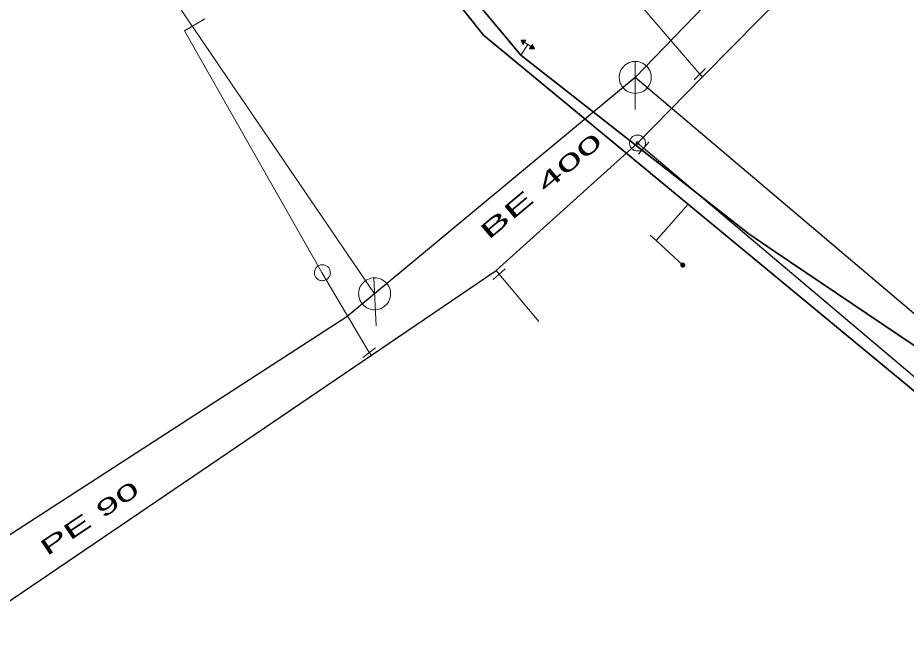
# Model space of a CAD drawing. Extents: x -779496 to -779026, y -977086 to -976624.
# Drawn here: x -779315.3 to -779259.7, y -976922.6 to -976883.2 of the extents above; entities that cross this region are included whole.
import ezdxf

# ---------------------------------------------------------------- set-up
doc = ezdxf.new("R2010")
doc.units = 0
doc.header["$LTSCALE"] = 0.4
doc.linetypes.add('MEDIUM_DASHED', pattern=[4.5, 3, -1.5])
for name, color, linetype, lineweight in [('1', 7, 'MEDIUM_DASHED', 25), ('11', 7, 'Continuous', 13), ('13', 7, 'Continuous', 13), ('14', 7, 'Continuous', 13), ('17', 7, 'Continuous', 25), ('22', 7, 'Continuous', 13), ('23', 7, 'Continuous', 13), ('34', 7, 'Continuous', 13), ('47', 7, 'Continuous', 13), ('9', 7, 'Continuous', 13)]:
    doc.layers.add(name, color=color, linetype=linetype, lineweight=lineweight)

msp = doc.modelspace()

# ---------------------------------------------------------------- linework, layer by layer
at = {"layer": '11'}
msp.add_line((-779306.139, -976881.166), (-779292.98, -976900.507), dxfattribs=at)
at = {"layer": '13'}
for p, q in [((-779272.656, -976886.759), (-779278.993, -976879.365)), ((-779293.314, -976904.181), (-779296.277, -976899.18)), ((-779282.71, -976902.234), (-779285.188, -976899.282))]:
    msp.add_line(p, q, dxfattribs=at)
msp.add_lwpolyline([(-779296.277, -976899.18), (-779304.857, -976884.055), (-779303.587, -976883.314)], dxfattribs=at)
at = {"layer": '14', "lineweight": 25}
for p, q in [((-779276.684, -976886.967), (-779292.98, -976900.507)), ((-779241.75, -976916.623), (-779276.684, -976886.967))]:
    msp.add_line(p, q, dxfattribs=at)
at = {"layer": '14'}
for p, q in [((-779272.473, -976886.943), (-779272.656, -976886.759)), ((-779276.545, -976891.073), (-779276.159, -976891.399)), ((-779273.375, -976894.904), (-779275.376, -976897.173)), ((-779275.376, -976897.173), (-779273.715, -976898.706)), ((-779285.388, -976899.059), (-779285.188, -976899.282)), ((-779293.182, -976904.354), (-779293.314, -976904.181))]:
    msp.add_line(p, q, dxfattribs=at)
at = {"layer": '14', "lineweight": 25}
for points in [[(-779257.611, -976867.208), (-779265.041, -976874.906), (-779276.684, -976886.967)], [(-779292.98, -976900.507), (-779294.713, -976901.947), (-779319.548, -976918.006), (-779350.848, -976937.607), (-779353.627, -976939.656), (-779370.105, -976951.862)]]:
    msp.add_lwpolyline(points, dxfattribs=at)
at = {"layer": '17'}
for points in [[(-779276.545, -976891.073), (-779272.473, -976886.943), (-779252.653, -976866.844), (-779246.603, -976859.784), (-779242.228, -976854.603), (-779234.164, -976845.175), (-779227.585, -976837.452), (-779212.579, -976818.883), (-779210.76, -976816.627), (-779191.487, -976792.772), (-779191.372, -976792.629), (-779190.682, -976791.787), (-779189.552, -976790.451), (-779187.15, -976792.396)], [(-779365.489, -976951.461), (-779357.531, -976946.544), (-779351.454, -976942.87), (-779336.305, -976933.651), (-779293.182, -976904.354), (-779285.388, -976899.059), (-779276.545, -976891.073)], [(-779226.798, -976933.215), (-779233.45, -976927.57), (-779243.764, -976918.817), (-779248.891, -976914.465), (-779251.398, -976912.338), (-779255.068, -976909.223), (-779276.159, -976891.399)]]:
    msp.add_lwpolyline(points, dxfattribs=at)
at = {"layer": '17', "lineweight": 35}
for points in [[(-779314.495, -976791.582), (-779291.37, -976876.552), (-779283.847, -976885.578)], [(-779294.52, -976873.809), (-779286.179, -976884.319), (-779226.903, -976933.326), (-779213.28, -976944.579), (-779208.355, -976950.874)], [(-779283.847, -976885.578), (-779269.588, -976896.763), (-779267.93, -976897.881), (-779206.76, -976939.131), (-779203.521, -976944.031)]]:
    msp.add_lwpolyline(points, dxfattribs=at)
at = {"layer": '22'}
for p, q in [((-779276.684, -976888.967), (-779276.683, -976885.967)), ((-779292.883, -976902.505), (-779293.028, -976899.508))]:
    msp.add_line(p, q, dxfattribs=at)
for points in [[(-779275.684, -976886.967), (-779275.689, -976886.858), (-779275.707, -976886.75), (-779275.737, -976886.644), (-779275.777, -976886.543), (-779275.829, -976886.446), (-779275.891, -976886.356), (-779275.963, -976886.273), (-779276.043, -976886.199), (-779276.131, -976886.133), (-779276.225, -976886.078), (-779276.325, -976886.033), (-779276.43, -976886), (-779276.537, -976885.978), (-779276.646, -976885.968), (-779276.756, -976885.97), (-779276.864, -976885.984), (-779276.971, -976886.009), (-779277.074, -976886.046), (-779277.172, -976886.095), (-779277.264, -976886.153), (-779277.35, -976886.222), (-779277.427, -976886.299), (-779277.496, -976886.385), (-779277.555, -976886.477), (-779277.603, -976886.575), (-779277.64, -976886.678), (-779277.666, -976886.785), (-779277.68, -976886.893), (-779277.683, -976887.003), (-779277.673, -976887.112), (-779277.652, -976887.219), (-779277.618, -976887.323), (-779277.574, -976887.423), (-779277.519, -976887.518), (-779277.453, -976887.606), (-779277.379, -976887.686), (-779277.296, -976887.758), (-779277.206, -976887.82), (-779277.11, -976887.872), (-779277.008, -976887.913), (-779276.903, -976887.943), (-779276.795, -976887.961), (-779276.685, -976887.967), (-779276.576, -976887.961), (-779276.468, -976887.943), (-779276.363, -976887.914), (-779276.261, -976887.873), (-779276.164, -976887.821), (-779276.074, -976887.759), (-779275.991, -976887.688), (-779275.916, -976887.608), (-779275.851, -976887.52), (-779275.795, -976887.426), (-779275.751, -976887.326), (-779275.717, -976887.222), (-779275.695, -976887.114), (-779275.685, -976887.005)], [(-779291.981, -976900.459), (-779291.992, -976900.35), (-779292.015, -976900.243), (-779292.05, -976900.139), (-779292.095, -976900.04), (-779292.152, -976899.945), (-779292.218, -976899.859), (-779292.294, -976899.779), (-779292.377, -976899.709), (-779292.468, -976899.647), (-779292.565, -976899.597), (-779292.667, -976899.557), (-779292.773, -976899.529), (-779292.881, -976899.512), (-779292.991, -976899.507), (-779293.1, -976899.515), (-779293.208, -976899.534), (-779293.313, -976899.564), (-779293.414, -976899.606), (-779293.51, -976899.66), (-779293.599, -976899.722), (-779293.682, -976899.795), (-779293.755, -976899.876), (-779293.82, -976899.965), (-779293.874, -976900.06), (-779293.917, -976900.16), (-779293.949, -976900.264), (-779293.97, -976900.373), (-779293.979, -976900.481), (-779293.976, -976900.591), (-779293.96, -976900.7), (-779293.934, -976900.805), (-779293.895, -976900.908), (-779293.846, -976901.005), (-779293.787, -976901.098), (-779293.717, -976901.182), (-779293.639, -976901.259), (-779293.553, -976901.327), (-779293.46, -976901.384), (-779293.361, -976901.431), (-779293.257, -976901.468), (-779293.151, -976901.492), (-779293.042, -976901.505), (-779292.932, -976901.506), (-779292.824, -976901.495), (-779292.717, -976901.471), (-779292.613, -976901.437), (-779292.513, -976901.392), (-779292.419, -976901.335), (-779292.332, -976901.269), (-779292.253, -976901.194), (-779292.181, -976901.11), (-779292.121, -976901.019), (-779292.069, -976900.923), (-779292.03, -976900.821), (-779292.001, -976900.715), (-779291.985, -976900.606), (-779291.98, -976900.497)]]:
    msp.add_lwpolyline(points, close=True, dxfattribs=at)
at = {"layer": '23'}
for points in [[(-779295.747, -976899.228), (-779295.745, -976899.177), (-779295.75, -976899.124), (-779295.758, -976899.073), (-779295.774, -976899.022), (-779295.794, -976898.975), (-779295.818, -976898.929), (-779295.848, -976898.886), (-779295.881, -976898.845), (-779295.919, -976898.809), (-779295.961, -976898.777), (-779296.005, -976898.749), (-779296.052, -976898.727), (-779296.102, -976898.71), (-779296.152, -976898.696), (-779296.203, -976898.69), (-779296.257, -976898.688), (-779296.309, -976898.692), (-779296.36, -976898.701), (-779296.41, -976898.717), (-779296.458, -976898.736), (-779296.505, -976898.76), (-779296.549, -976898.79), (-779296.589, -976898.824), (-779296.623, -976898.862), (-779296.656, -976898.903), (-779296.683, -976898.947), (-779296.706, -976898.996), (-779296.723, -976899.044), (-779296.735, -976899.095), (-779296.743, -976899.147), (-779296.745, -976899.199), (-779296.741, -976899.251), (-779296.731, -976899.304), (-779296.717, -976899.353), (-779296.697, -976899.401), (-779296.673, -976899.447), (-779296.642, -976899.491), (-779296.61, -976899.53), (-779296.57, -976899.567)], [(-779296.505, -976898.76), (-779296.549, -976898.79), (-779296.589, -976898.824), (-779296.623, -976898.862), (-779296.656, -976898.903), (-779296.683, -976898.947), (-779296.706, -976898.996), (-779296.723, -976899.044), (-779296.735, -976899.095), (-779296.743, -976899.147), (-779296.745, -976899.199), (-779296.741, -976899.251), (-779296.731, -976899.304), (-779296.717, -976899.353), (-779296.697, -976899.401), (-779296.673, -976899.447), (-779296.642, -976899.491), (-779296.61, -976899.53), (-779296.57, -976899.567), (-779296.531, -976899.599), (-779296.486, -976899.627), (-779296.437, -976899.649), (-779296.388, -976899.667), (-779296.337, -976899.679), (-779296.286, -976899.687), (-779296.234, -976899.688), (-779296.181, -976899.683), (-779296.13, -976899.674), (-779296.08, -976899.659), (-779296.032, -976899.639), (-779295.985, -976899.615), (-779295.942, -976899.586), (-779295.902, -976899.552), (-779295.865, -976899.514), (-779295.834, -976899.473), (-779295.808, -976899.428), (-779295.785, -976899.381), (-779295.766, -976899.332), (-779295.754, -976899.28), (-779295.747, -976899.228)], [(-779296.57, -976899.567), (-779296.531, -976899.599), (-779296.486, -976899.627), (-779296.437, -976899.649), (-779296.388, -976899.667), (-779296.337, -976899.679), (-779296.286, -976899.687), (-779296.234, -976899.688), (-779296.181, -976899.683), (-779296.13, -976899.674), (-779296.08, -976899.659), (-779296.032, -976899.639), (-779295.985, -976899.615), (-779295.942, -976899.586), (-779295.902, -976899.552), (-779295.865, -976899.514), (-779295.834, -976899.473), (-779295.808, -976899.428), (-779295.785, -976899.381), (-779295.766, -976899.332), (-779295.754, -976899.28), (-779295.747, -976899.228), (-779295.745, -976899.177), (-779295.75, -976899.124), (-779295.758, -976899.073), (-779295.774, -976899.022), (-779295.794, -976898.975), (-779295.818, -976898.929), (-779295.848, -976898.886), (-779295.881, -976898.845), (-779295.919, -976898.809), (-779295.961, -976898.777), (-779296.005, -976898.749), (-779296.052, -976898.727), (-779296.102, -976898.71), (-779296.152, -976898.696), (-779296.203, -976898.69), (-779296.257, -976898.688), (-779296.309, -976898.692), (-779296.36, -976898.701)], [(-779296.36, -976898.701), (-779296.41, -976898.717), (-779296.458, -976898.736), (-779296.505, -976898.76)]]:
    msp.add_lwpolyline(points, dxfattribs=at)
at = {"layer": '34'}
for p, q in [((-779283.404, -976884.91), (-779283.846, -976885.577)), ((-779283.705, -976884.912), (-779283.817, -976884.636)), ((-779283.789, -976884.636), (-779283.807, -976884.662)), ((-779283.757, -976884.639), (-779283.793, -976884.691)), ((-779283.726, -976884.637), (-779283.784, -976884.721)), ((-779283.698, -976884.636), (-779283.773, -976884.747)), ((-779283.667, -976884.639), (-779283.76, -976884.776)), ((-779283.639, -976884.638), (-779283.749, -976884.801)), ((-779283.61, -976884.64), (-779283.738, -976884.828)), ((-779283.579, -976884.636), (-779283.729, -976884.858)), ((-779283.548, -976884.639), (-779283.716, -976884.886)), ((-779283.098, -976884.937), (-779283.261, -976885.188)), ((-779283.084, -976884.964), (-779283.229, -976885.19)), ((-779283.075, -976884.994), (-779283.198, -976885.186)), ((-779283.062, -976885.021), (-779283.169, -976885.186)), ((-779283.052, -976885.047), (-779283.142, -976885.186)), ((-779283.037, -976885.075), (-779283.11, -976885.187)), ((-779283.026, -976885.101), (-779283.082, -976885.186)), ((-779283.017, -976885.13), (-779283.051, -976885.183)), ((-779283.001, -976885.158), (-779283.019, -976885.185)), ((-779273.009, -976887.112), (-779272.301, -976886.406)), ((-779275.832, -976891.02), (-779276.486, -976891.776)), ((-779275, -976897.503), (-779275.75, -976896.841)), ((-779284.816, -976898.946), (-779285.559, -976899.616)), ((-779293.711, -976904.483), (-779292.915, -976903.878))]:
    msp.add_line(p, q, dxfattribs=at)
for points in [[(-779283.817, -976884.636), (-779283.519, -976884.639), (-779283.705, -976884.912)], [(-779283.289, -976885.189), (-779282.991, -976885.184), (-779283.817, -976884.636)], [(-779282.991, -976885.184), (-779283.109, -976884.91), (-779283.289, -976885.189)]]:
    msp.add_lwpolyline(points, dxfattribs=at)
at = {"layer": '47'}
for points in [[(-779276.182, -976890.728), (-779276.22, -976890.693), (-779276.262, -976890.66), (-779276.306, -976890.634), (-779276.353, -976890.611), (-779276.403, -976890.593), (-779276.454, -976890.581), (-779276.506, -976890.575), (-779276.558, -976890.573), (-779276.61, -976890.577), (-779276.661, -976890.586), (-779276.712, -976890.601), (-779276.76, -976890.622), (-779276.806, -976890.646), (-779276.849, -976890.676), (-779276.889, -976890.71), (-779276.924, -976890.748), (-779276.957, -976890.79), (-779276.984, -976890.835), (-779277.006, -976890.881), (-779277.024, -976890.931), (-779277.036, -976890.982), (-779277.043, -976891.034), (-779277.044, -976891.087), (-779277.041, -976891.138), (-779277.031, -976891.189), (-779277.016, -976891.24), (-779276.996, -976891.289), (-779276.971, -976891.334), (-779276.941, -976891.377), (-779276.907, -976891.417), (-779276.869, -976891.452), (-779276.827, -976891.485), (-779276.783, -976891.513), (-779276.736, -976891.534), (-779276.686, -976891.552), (-779276.636, -976891.565), (-779276.583, -976891.572), (-779276.531, -976891.573), (-779276.479, -976891.569), (-779276.428, -976891.559), (-779276.377, -976891.544), (-779276.329, -976891.524), (-779276.283, -976891.499), (-779276.24, -976891.469), (-779276.2, -976891.435), (-779276.165, -976891.397), (-779276.132, -976891.355), (-779276.105, -976891.312), (-779276.083, -976891.264), (-779276.065, -976891.214), (-779276.052, -976891.164), (-779276.046, -976891.112), (-779276.045, -976891.06), (-779276.049, -976891.007), (-779276.058, -976890.956), (-779276.073, -976890.905), (-779276.093, -976890.858), (-779276.118, -976890.811), (-779276.148, -976890.768)], [(-779276.485, -976891.016), (-779276.491, -976891.01), (-779276.498, -976891.005), (-779276.505, -976891.001), (-779276.513, -976890.997), (-779276.521, -976890.994), (-779276.53, -976890.992), (-779276.538, -976890.991), (-779276.547, -976890.99), (-779276.555, -976890.992), (-779276.564, -976890.993), (-779276.572, -976890.995), (-779276.58, -976890.999), (-779276.587, -976891.003), (-779276.594, -976891.007), (-779276.601, -976891.013), (-779276.607, -976891.019), (-779276.612, -976891.026), (-779276.616, -976891.033), (-779276.62, -976891.041), (-779276.623, -976891.049), (-779276.625, -976891.058), (-779276.626, -976891.066), (-779276.627, -976891.075), (-779276.626, -976891.084), (-779276.624, -976891.092), (-779276.622, -976891.1), (-779276.618, -976891.108), (-779276.614, -976891.115), (-779276.61, -976891.122), (-779276.604, -976891.129), (-779276.598, -976891.135), (-779276.591, -976891.14), (-779276.584, -976891.144), (-779276.576, -976891.148), (-779276.568, -976891.151), (-779276.56, -976891.153), (-779276.551, -976891.154), (-779276.542, -976891.155), (-779276.533, -976891.154), (-779276.525, -976891.152), (-779276.517, -976891.15), (-779276.509, -976891.146), (-779276.502, -976891.142), (-779276.495, -976891.138), (-779276.488, -976891.132), (-779276.482, -976891.126), (-779276.477, -976891.119), (-779276.473, -976891.112), (-779276.469, -976891.104), (-779276.466, -976891.096), (-779276.464, -976891.088), (-779276.463, -976891.079), (-779276.462, -976891.07), (-779276.464, -976891.062), (-779276.465, -976891.053), (-779276.467, -976891.045), (-779276.471, -976891.037), (-779276.475, -976891.03), (-779276.479, -976891.023)]]:
    msp.add_lwpolyline(points, close=True, dxfattribs=at)
at = {"layer": '9'}
for points in [[(-779273.841, -976898.706), (-779273.841, -976898.719), (-779273.838, -976898.732), (-779273.836, -976898.745), (-779273.831, -976898.757), (-779273.825, -976898.769), (-779273.818, -976898.78), (-779273.809, -976898.79), (-779273.799, -976898.8), (-779273.789, -976898.808), (-779273.779, -976898.815), (-779273.767, -976898.821), (-779273.755, -976898.826), (-779273.742, -976898.829), (-779273.728, -976898.831), (-779273.716, -976898.833), (-779273.703, -976898.832), (-779273.69, -976898.83), (-779273.677, -976898.827), (-779273.664, -976898.822), (-779273.652, -976898.816), (-779273.642, -976898.809), (-779273.632, -976898.801), (-779273.622, -976898.791), (-779273.614, -976898.781), (-779273.607, -976898.77), (-779273.601, -976898.758), (-779273.596, -976898.746), (-779273.593, -976898.733), (-779273.591, -976898.72), (-779273.588, -976898.707), (-779273.59, -976898.694), (-779273.592, -976898.681), (-779273.595, -976898.668), (-779273.6, -976898.656), (-779273.605, -976898.644), (-779273.613, -976898.633), (-779273.62, -976898.623), (-779273.63, -976898.613), (-779273.641, -976898.605), (-779273.652, -976898.598), (-779273.664, -976898.592), (-779273.676, -976898.587), (-779273.689, -976898.584), (-779273.701, -976898.582), (-779273.715, -976898.581), (-779273.728, -976898.581), (-779273.74, -976898.583), (-779273.754, -976898.586), (-779273.766, -976898.591), (-779273.777, -976898.597), (-779273.789, -976898.604), (-779273.799, -976898.612), (-779273.809, -976898.622), (-779273.816, -976898.632), (-779273.824, -976898.643), (-779273.83, -976898.655), (-779273.835, -976898.667), (-779273.838, -976898.68), (-779273.84, -976898.693)], [(-779273.821, -976898.706), (-779273.821, -976898.717), (-779273.82, -976898.728), (-779273.816, -976898.739), (-779273.813, -976898.749), (-779273.808, -976898.759), (-779273.802, -976898.768), (-779273.794, -976898.777), (-779273.787, -976898.785), (-779273.777, -976898.792), (-779273.769, -976898.798), (-779273.759, -976898.803), (-779273.749, -976898.807), (-779273.738, -976898.81), (-779273.727, -976898.813), (-779273.716, -976898.813), (-779273.705, -976898.813), (-779273.694, -976898.811), (-779273.683, -976898.808), (-779273.673, -976898.804), (-779273.663, -976898.799), (-779273.654, -976898.793), (-779273.645, -976898.786), (-779273.637, -976898.778), (-779273.63, -976898.769), (-779273.624, -976898.76), (-779273.619, -976898.75), (-779273.615, -976898.74), (-779273.612, -976898.729), (-779273.61, -976898.718), (-779273.608, -976898.707), (-779273.608, -976898.696), (-779273.61, -976898.685), (-779273.614, -976898.674), (-779273.618, -976898.664), (-779273.623, -976898.654), (-779273.629, -976898.645), (-779273.636, -976898.636), (-779273.644, -976898.628), (-779273.652, -976898.621), (-779273.662, -976898.615), (-779273.672, -976898.61), (-779273.681, -976898.606), (-779273.693, -976898.603), (-779273.703, -976898.601), (-779273.715, -976898.601), (-779273.726, -976898.6), (-779273.737, -976898.602), (-779273.748, -976898.605), (-779273.757, -976898.609), (-779273.767, -976898.614), (-779273.777, -976898.62), (-779273.786, -976898.627), (-779273.794, -976898.635), (-779273.801, -976898.644), (-779273.806, -976898.653), (-779273.811, -976898.663), (-779273.816, -976898.673), (-779273.819, -976898.684), (-779273.821, -976898.695)], [(-779273.802, -976898.706), (-779273.802, -976898.715), (-779273.801, -976898.724), (-779273.798, -976898.733), (-779273.794, -976898.741), (-779273.791, -976898.749), (-779273.786, -976898.757), (-779273.779, -976898.764), (-779273.774, -976898.77), (-779273.767, -976898.776), (-779273.759, -976898.781), (-779273.75, -976898.785), (-779273.743, -976898.788), (-779273.733, -976898.791), (-779273.725, -976898.792), (-779273.716, -976898.794), (-779273.706, -976898.793), (-779273.698, -976898.792), (-779273.689, -976898.789), (-779273.681, -976898.786), (-779273.673, -976898.782), (-779273.664, -976898.777), (-779273.657, -976898.771), (-779273.652, -976898.765), (-779273.646, -976898.758), (-779273.641, -976898.75), (-779273.637, -976898.742), (-779273.634, -976898.734), (-779273.63, -976898.725), (-779273.63, -976898.716), (-779273.627, -976898.707), (-779273.629, -976898.698), (-779273.63, -976898.689), (-779273.632, -976898.68), (-779273.636, -976898.672), (-779273.64, -976898.664), (-779273.645, -976898.656), (-779273.651, -976898.649), (-779273.657, -976898.643), (-779273.664, -976898.637), (-779273.672, -976898.632), (-779273.679, -976898.628), (-779273.688, -976898.625), (-779273.696, -976898.622), (-779273.706, -976898.621), (-779273.715, -976898.62), (-779273.723, -976898.62), (-779273.733, -976898.621), (-779273.742, -976898.624), (-779273.75, -976898.627), (-779273.757, -976898.631), (-779273.766, -976898.636), (-779273.772, -976898.642), (-779273.779, -976898.648), (-779273.784, -976898.655), (-779273.789, -976898.663), (-779273.794, -976898.671), (-779273.797, -976898.679), (-779273.799, -976898.688), (-779273.801, -976898.697)], [(-779273.782, -976898.706), (-779273.782, -976898.713), (-779273.781, -976898.72), (-779273.779, -976898.727), (-779273.777, -976898.733), (-779273.774, -976898.739), (-779273.77, -976898.745), (-779273.766, -976898.751), (-779273.761, -976898.756), (-779273.755, -976898.76), (-779273.749, -976898.764), (-779273.743, -976898.767), (-779273.737, -976898.77), (-779273.73, -976898.771), (-779273.723, -976898.774), (-779273.716, -976898.774), (-779273.708, -976898.774), (-779273.701, -976898.772), (-779273.695, -976898.771), (-779273.689, -976898.768), (-779273.681, -976898.765), (-779273.677, -976898.761), (-779273.671, -976898.757), (-779273.666, -976898.752), (-779273.662, -976898.746), (-779273.657, -976898.74), (-779273.654, -976898.734), (-779273.652, -976898.728), (-779273.65, -976898.721), (-779273.649, -976898.714), (-779273.647, -976898.707), (-779273.647, -976898.7), (-779273.649, -976898.693), (-779273.651, -976898.686), (-779273.654, -976898.68), (-779273.657, -976898.673), (-779273.661, -976898.668), (-779273.664, -976898.662), (-779273.669, -976898.657), (-779273.676, -976898.653), (-779273.681, -976898.649), (-779273.688, -976898.646), (-779273.694, -976898.643), (-779273.701, -976898.641), (-779273.708, -976898.64), (-779273.715, -976898.64), (-779273.722, -976898.64), (-779273.728, -976898.64), (-779273.735, -976898.642), (-779273.742, -976898.645), (-779273.748, -976898.648), (-779273.754, -976898.652), (-779273.76, -976898.656), (-779273.765, -976898.661), (-779273.769, -976898.667), (-779273.772, -976898.672), (-779273.776, -976898.679), (-779273.779, -976898.685), (-779273.779, -976898.692), (-779273.782, -976898.699)], [(-779273.762, -976898.706), (-779273.762, -976898.711), (-779273.762, -976898.716), (-779273.761, -976898.721), (-779273.759, -976898.725), (-779273.757, -976898.73), (-779273.754, -976898.734), (-779273.75, -976898.737), (-779273.747, -976898.741), (-779273.744, -976898.744), (-779273.74, -976898.747), (-779273.735, -976898.749), (-779273.73, -976898.751), (-779273.726, -976898.752), (-779273.721, -976898.754), (-779273.716, -976898.754), (-779273.711, -976898.754), (-779273.706, -976898.753), (-779273.701, -976898.752), (-779273.696, -976898.75), (-779273.691, -976898.748), (-779273.688, -976898.745), (-779273.684, -976898.742), (-779273.681, -976898.738), (-779273.678, -976898.735), (-779273.674, -976898.731), (-779273.673, -976898.726), (-779273.671, -976898.722), (-779273.669, -976898.717), (-779273.669, -976898.712), (-779273.668, -976898.707), (-779273.668, -976898.702), (-779273.669, -976898.697), (-779273.669, -976898.692), (-779273.672, -976898.688), (-779273.674, -976898.683), (-779273.677, -976898.679), (-779273.679, -976898.675), (-779273.683, -976898.672), (-779273.686, -976898.669), (-779273.691, -976898.666), (-779273.696, -976898.664), (-779273.7, -976898.662), (-779273.705, -976898.661), (-779273.71, -976898.66), (-779273.715, -976898.66), (-779273.72, -976898.66), (-779273.725, -976898.661), (-779273.73, -976898.661), (-779273.733, -976898.663), (-779273.739, -976898.665), (-779273.743, -976898.668), (-779273.745, -976898.671), (-779273.75, -976898.674), (-779273.752, -976898.678), (-779273.755, -976898.682), (-779273.757, -976898.687), (-779273.76, -976898.691), (-779273.761, -976898.696), (-779273.762, -976898.701)], [(-779273.742, -976898.706), (-779273.742, -976898.709), (-779273.743, -976898.712), (-779273.742, -976898.714), (-779273.74, -976898.717), (-779273.74, -976898.72), (-779273.738, -976898.722), (-779273.735, -976898.724), (-779273.733, -976898.726), (-779273.732, -976898.728), (-779273.73, -976898.73), (-779273.727, -976898.732), (-779273.723, -976898.733), (-779273.722, -976898.733), (-779273.718, -976898.734), (-779273.716, -976898.734), (-779273.713, -976898.734), (-779273.71, -976898.734), (-779273.706, -976898.733), (-779273.705, -976898.732), (-779273.701, -976898.731), (-779273.7, -976898.729), (-779273.696, -976898.727), (-779273.695, -976898.725), (-779273.694, -976898.723), (-779273.691, -976898.721), (-779273.691, -976898.718), (-779273.689, -976898.715), (-779273.689, -976898.713), (-779273.688, -976898.71), (-779273.686, -976898.707), (-779273.688, -976898.704), (-779273.688, -976898.701), (-779273.689, -976898.698), (-779273.69, -976898.696), (-779273.691, -976898.693), (-779273.693, -976898.691), (-779273.694, -976898.688), (-779273.696, -976898.686), (-779273.699, -976898.685), (-779273.701, -976898.683), (-779273.703, -976898.682), (-779273.706, -976898.681), (-779273.708, -976898.68), (-779273.712, -976898.68), (-779273.715, -976898.679), (-779273.718, -976898.68), (-779273.721, -976898.679), (-779273.723, -976898.681), (-779273.726, -976898.681), (-779273.728, -976898.682), (-779273.73, -976898.684), (-779273.733, -976898.685), (-779273.735, -976898.687), (-779273.737, -976898.69), (-779273.739, -976898.692), (-779273.74, -976898.695), (-779273.74, -976898.697), (-779273.742, -976898.7), (-779273.742, -976898.703)], [(-779273.723, -976898.706), (-779273.723, -976898.708), (-779273.723, -976898.708), (-779273.722, -976898.708), (-779273.722, -976898.71), (-779273.723, -976898.711), (-779273.721, -976898.711), (-779273.721, -976898.711), (-779273.721, -976898.713), (-779273.721, -976898.713), (-779273.72, -976898.714), (-779273.718, -976898.714), (-779273.718, -976898.714), (-779273.718, -976898.715), (-779273.716, -976898.715), (-779273.716, -976898.715), (-779273.715, -976898.715), (-779273.713, -976898.715), (-779273.713, -976898.714), (-779273.713, -976898.714), (-779273.711, -976898.714), (-779273.711, -976898.713), (-779273.711, -976898.713), (-779273.71, -976898.712), (-779273.71, -976898.712), (-779273.708, -976898.711), (-779273.708, -976898.71), (-779273.706, -976898.709), (-779273.706, -976898.709), (-779273.706, -976898.708), (-779273.706, -976898.707), (-779273.706, -976898.706), (-779273.706, -976898.705), (-779273.706, -976898.705), (-779273.708, -976898.704), (-779273.708, -976898.703), (-779273.708, -976898.702), (-779273.708, -976898.702), (-779273.71, -976898.701), (-779273.71, -976898.701), (-779273.711, -976898.7), (-779273.712, -976898.7), (-779273.713, -976898.699), (-779273.713, -976898.699), (-779273.713, -976898.699), (-779273.715, -976898.699), (-779273.716, -976898.699), (-779273.717, -976898.699), (-779273.717, -976898.699), (-779273.718, -976898.7), (-779273.718, -976898.699), (-779273.72, -976898.701), (-779273.72, -976898.701), (-779273.721, -976898.701), (-779273.721, -976898.701), (-779273.722, -976898.703), (-779273.722, -976898.704), (-779273.722, -976898.705), (-779273.723, -976898.705), (-779273.723, -976898.706)]]:
    msp.add_lwpolyline(points, close=True, dxfattribs=at)

# ---------------------------------------------------------------- texts
at = {"layer": '1'}
for s, rotation, width, p in [('BE 400', 40, 2.15, (-779285.87, -976897.18)), ('PE 90 ', 34, 1.95, (-779313.467, -976916.944))]:
    msp.add_text(s, height=1, rotation=rotation, dxfattribs=dict(at, width=width)).set_placement(p)

doc.saveas('drawing.dxf')
